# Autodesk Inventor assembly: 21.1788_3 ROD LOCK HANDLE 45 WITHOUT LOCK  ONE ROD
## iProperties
Created: 2007-03
Part Number: 21.1788_3 ROD LOCK HANDLE 45 WITHOUT LOCK  ONE ROD
Document SubType Name: Assembly
Designer: Andy Moles
Author: Andy Moles
